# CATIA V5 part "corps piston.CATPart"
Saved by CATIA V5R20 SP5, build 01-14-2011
Part number: corps piston
Bounding box of the stored display mesh (mm): x 3181.281 to 9761.784, y -900 to 834.832, z 8622.058 to 11602.592
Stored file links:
  M:\EU_thinkMotion\IAO_2010\iao\IAO_MMS_Groupe1\Problemes\gduval\Gduval\train d'aterrissage squelette + piece kinematic\corps piston.CATPart
  M:\EU_thinkMotion\IAO_2010\iao\IAO_MMS_Groupe1\Problemes\gduval\Gduval\train d'aterrissage squelette + piece kinematic\train d'aterrissage.CATProduct
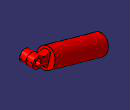
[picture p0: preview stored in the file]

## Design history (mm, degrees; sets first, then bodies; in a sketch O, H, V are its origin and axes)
External parameters (linked from other documents)
  `External.diamètre piston` = 835 mm
Body1 (main body)
  Point1: stored without definition
  Point2: stored without definition
  Sketch1 on zx-plane, origin (0, 0, 0), H (-1, 0, 0), V (0, 0, 1)
    arc A1 centre (-9261.784, 11081.702) radius 500 from (-8794.3013, 11259.0714) to (-9742.8915, 11217.8475) ccw
    point P1 (-9261.784, 11081.702)
    point P2 (-8794.3013, 11259.0714)
    point P3 (-9742.8915, 11217.8475)
    reference projected point E1 (-9261.784, 11081.702) from Point1
    axis line L1 (604.2237, 8289.7836) -> (-10989.4886, 11570.6141)
    reference projected point E2 (-9261.784, 11081.702) from Point1
    reference projected point E3 (0, 8460.769) from Point2
    line L2 (-8794.3013, 11259.0714) -> (-8100.6585, 11375.9854)
    point P6 (-8100.6585, 11375.9854)
    line L3 (-8100.6585, 11375.9854) -> (-8263.8501, 10799.3031)
    point P7 (-8100.6585, 11375.9854)
    point P8 (-8263.8501, 10799.3031)
    point P9 (-9742.8915, 11217.8475)
    point P10 (-8956.5643, 10685.6705)
    arc A2 centre (-9261.784, 11081.702) radius 500 from (-8956.5643, 10685.6705) to (-9742.8915, 11217.8475) cw
    point P12 (-8427.0417, 10222.6208)
    line L4 (-8956.5643, 10685.6705) -> (-8427.0417, 10222.6208)
    point P13 (-8263.8501, 10799.3031)
    point P14 (-8427.0417, 10222.6208)
    line L5 (-8427.0417, 10222.6208) -> (-8263.8501, 10799.3031)
    radius A1 = 500
    coincidence: P1 E1, L1 P1, L1 E2, L1 E3, P3 L1, P8 L1, P7 P6, P3 P9, P8 P13, P12 P14
    perpendicularity: L3 L1
    symmetry: P3 P9 L1, P2 P10 L1, A1 A2 L1, P6 P12 L1, L2 L4 L1, P8 P13 L1, P7 P14 L1, L3 L5 L1
  Pad1: profile Sketch1, direction (0, 1, 0), length 300, mirrored extent
  Sketch2 on zx-plane, origin (0, 0, 0), H (-1, 0, 0), V (0, 0, 1)
    line L1 (-8036.4871, 11602.7525) -> (-3181.2348, 10228.7958)
    point P1 (-8036.4871, 11602.7525)
    line L2 (-6097.0592, 10497.9174) -> (-3210.4144, 9681.0443)
    point P4 (-3210.4144, 9681.0443)
    line L3 (-3181.2348, 10228.7958) -> (-3210.4144, 9681.0443)
    point P5 (-3210.4144, 9681.0443)
    axis line L4 (2214.4028, 7834.1293) -> (-11794.3386, 11798.3734)
    reference projected point E1 (-9261.784, 11081.702) from Point1
    reference projected point E2 (0, 8460.769) from Point2
    line L5 (-6097.0592, 10497.9174) -> (-6178.7465, 10209.2529)
    point P8 (-6178.7465, 10209.2529)
    reference projected line E3 (-8263.8501, 10799.3031) -> (-8100.6585, 11375.9854) from edge [face of Pad1 from Sketch1.L3 | end face of Pad1]
    line L6 (-8263.8501, 10799.3031) -> (-8036.4871, 11602.7525)
    point P9 (-8263.8501, 10799.3031)
    line L7 (-8263.8501, 10799.3031) -> (-6178.7465, 10209.2529)
    distance L2 L4 = 300
    length L2 = 3000
    length L1 = 5045.9124
    distance L1 L4 = 835 {= `External.diamètre piston`}
    distance P4 L6 = 5166.9832
    parallelism: L2 L1, L7 L4
    coincidence: P5 P4, L4 E1, E2 L4, P8 L4, P1 E3, P9 L4
    perpendicularity: L5 L4, L6 L1
  Shaft1: profile Sketch2, axis Sketch2.L4, angle 360
  Sketch3 on end face of Pad1, origin (9023.6055, 300, 10958.0576), H (1, 0, 0), V (0, 0, -1)
    point P1 (238.1785, -123.6444)
    reference projected arc E1 centre (238.1785, -123.6444) radius 500 from (719.286, -259.7899) to (-67.0411, 272.3871) ccw from edge [face of Pad1 from Sketch1.A2 | end face of Pad1]
    concentricity: P1 E1
  Hole1: placed by Sketch3, at (9261.784, 300, 11081.702) direction (0, -1, 0), diameter 520, through (limit type 6)
  Sketch4 on start face of Pad1, origin (0, -300, 0), H (1, 0, 0), V (0, 0, 1)
    circle A1 centre (9261.784, 11081.702) radius 500
    reference projected arc E1 centre (9261.784, 11081.702) radius 500 from (9742.8915, 11217.8475) to (8794.3013, 11259.0714) ccw from edge [start face of Pad1 | face of Pad1 from Sketch1.A1]
    circle A2 centre (9261.784, 11081.702) radius 260
    reference projected circle E2 centre (9261.784, 11081.702) radius 260 from edge [face of Hole1 | start face of Pad1]
    coincidence: A1 E1, A2 E2
  Pad2: profile Sketch4, direction (0, -1, 0), length 600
